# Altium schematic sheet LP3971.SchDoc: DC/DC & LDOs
size 419 x 266 mm; Date: May 24, 2007; DrawnBy: Yossi Har-Nov; Engineer: Yossi Har-Nov; DocumentNumber: 1; Revision: 1.0; SheetNumber: 1; SheetTotal: 3; PageSetup: Record=PageOptions|CenterHorizontal=True|CenterVertical=True|PrintScale=0.66|XCorrection=1.00|YCorrection=1.00|PrintKind=1|BorderSize=5000000|LeftOffset=0|BottomOffset=0|Orientation=2|PaperLength=2794|PaperWidth=2159|Scale=100|PaperSource=7|PrintQuality=600|MediaType=1|DitherType=2|PaperKind=Letter|PrintScaleMode=1
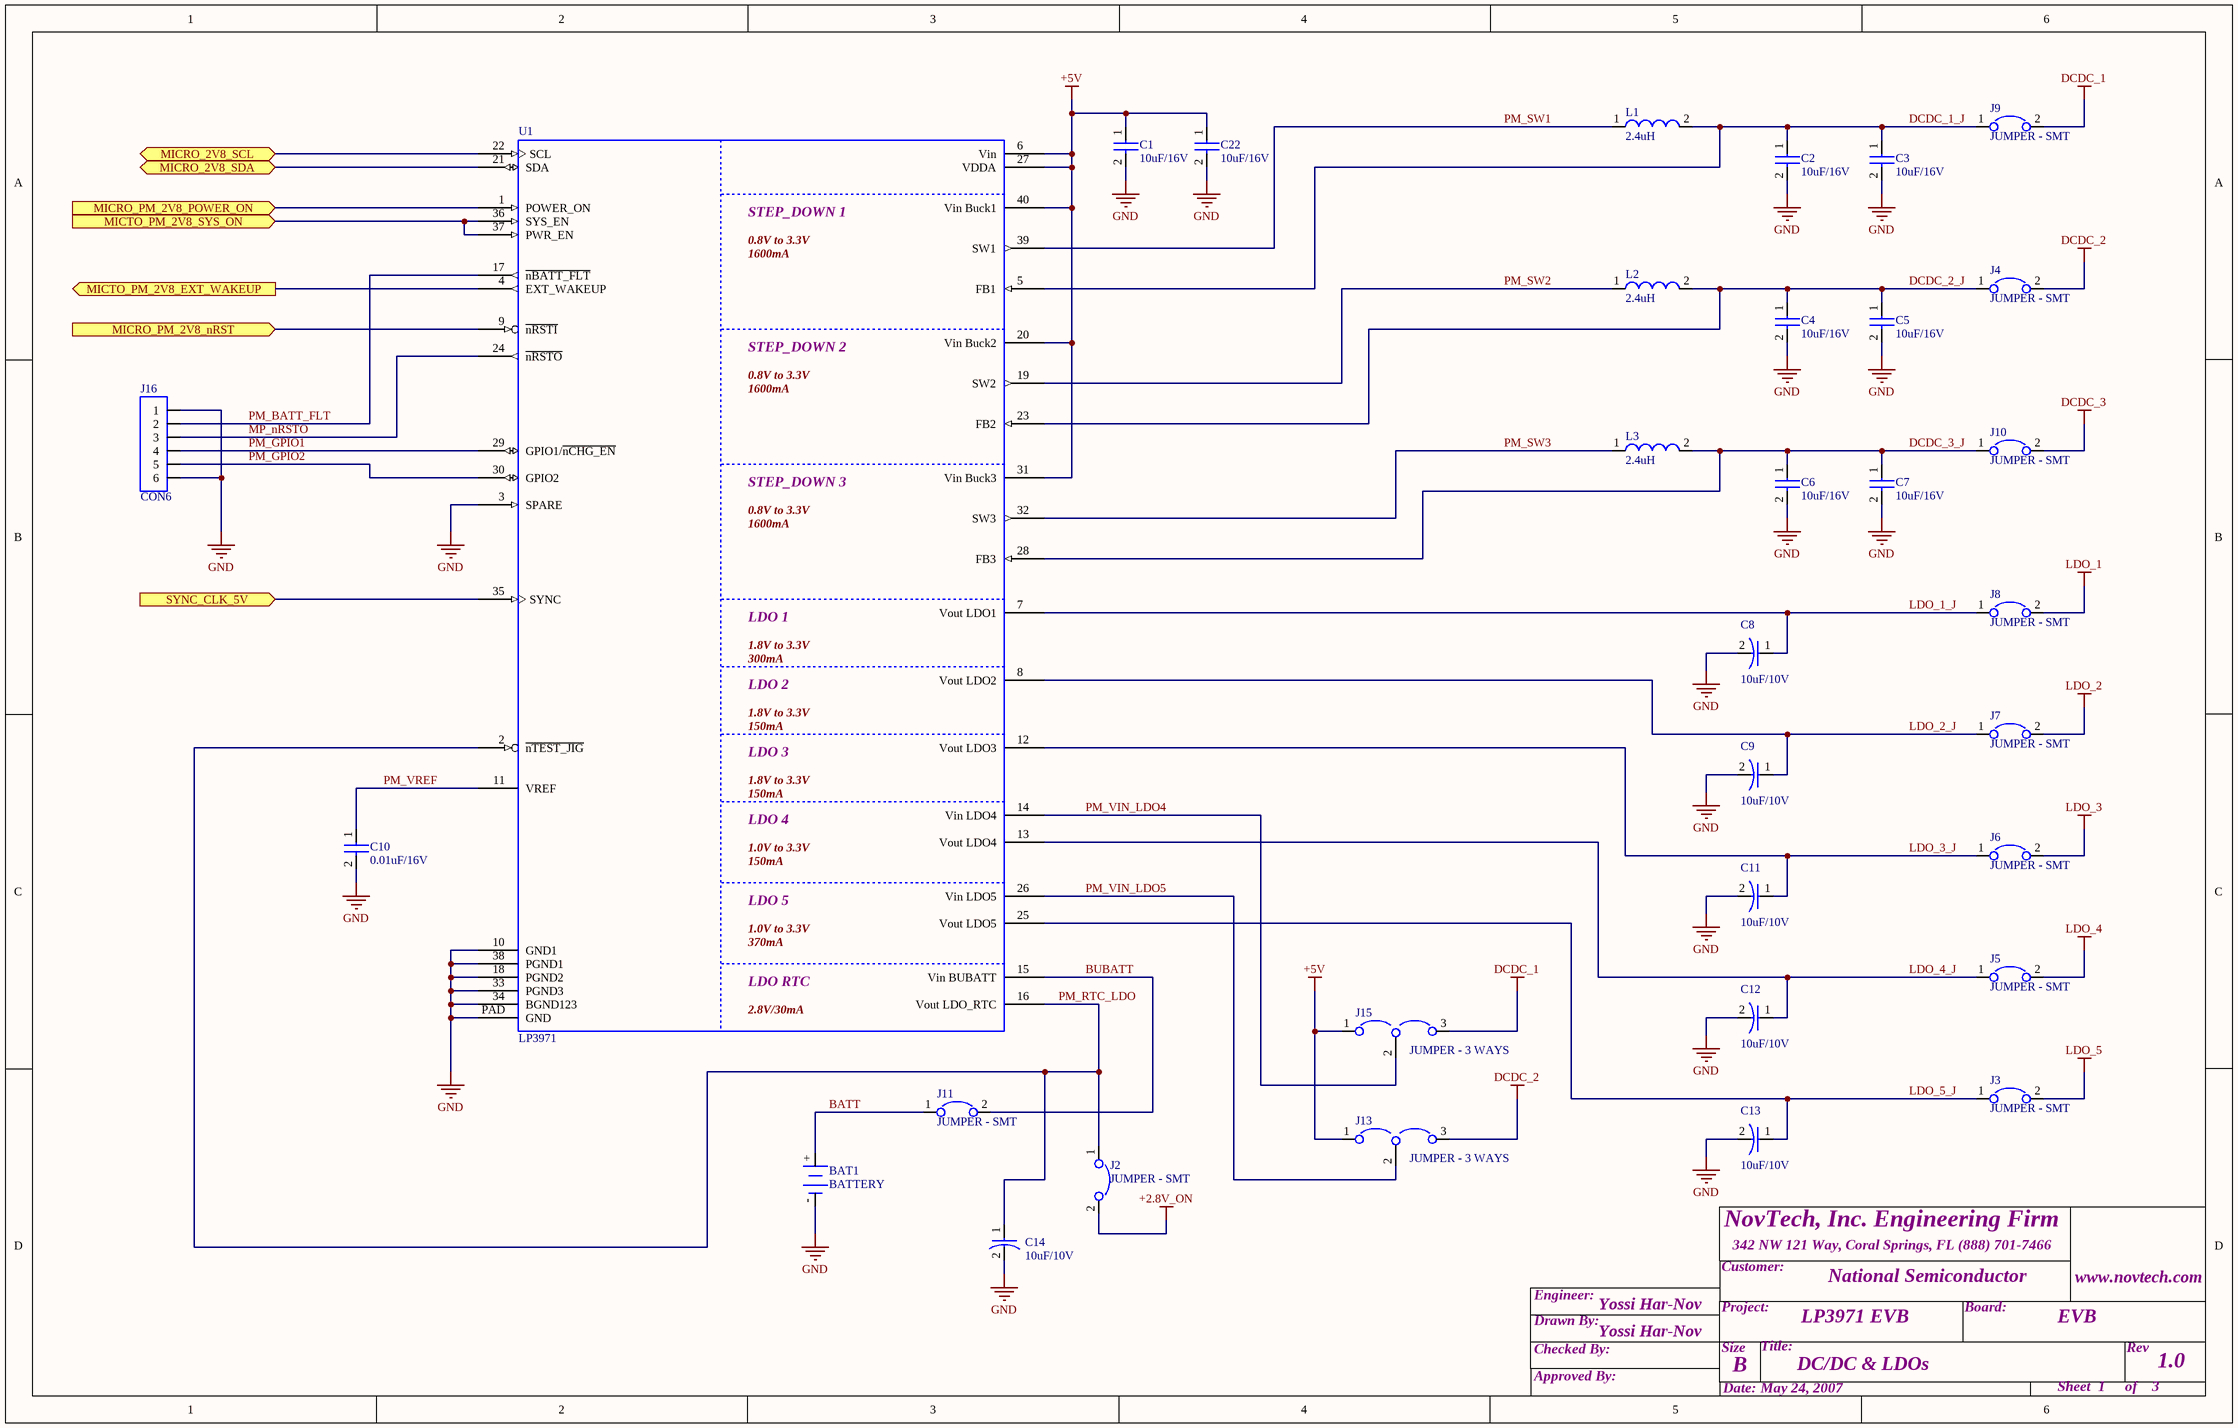
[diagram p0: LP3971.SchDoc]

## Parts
BAT1  BATTERY  [BATTERY ML2020]
C1  10uF/16V  [1210_C]
C2  10uF/16V  [1210_C]
C3  10uF/16V  [1210_C]
C4  10uF/16V  [1210_C]
C5  10uF/16V  [1210_C]
C6  10uF/16V  [1210_C]
C7  10uF/16V  [1210_C]
C8  10uF/10V  [A CASE (3216-18)]
C9  10uF/10V  [A CASE (3216-18)]
C10  0.01uF/16V  [0603_C]
C11  10uF/10V  [A CASE (3216-18)]
C12  10uF/10V  [A CASE (3216-18)]
C13  10uF/10V  [A CASE (3216-18)]
C14  10uF/10V  [A CASE (3216-18)]
C22  10uF/16V  [1210_C]
J2  JUMPER - SMT  [BH2-NP]
J3  JUMPER - SMT  [BH2-NP]
J4  JUMPER - SMT  [BH2-NP]
J5  JUMPER - SMT  [BH2-NP]
J6  JUMPER - SMT  [BH2-NP]
J7  JUMPER - SMT  [BH2-NP]
J8  JUMPER - SMT  [BH2-NP]
J9  JUMPER - SMT  [BH2-NP]
J10  JUMPER - SMT  [BH2-NP]
J11  JUMPER - SMT  [BH2-NP]
J13  JUMPER - 3 WAYS  [BH3-NP]
J15  JUMPER - 3 WAYS  [BH3-NP]
J16  CON6  [BH6-NP]
L1  2.4uH  [ELL6PM]
L2  2.4uH  [ELL6PM]
L3  2.4uH  [ELL6PM]
U1  LP3971  [QFN40P500X500X80-40N]

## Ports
MICRO_2V8_SCL (bidir), MICRO_2V8_SDA (bidir), MICRO_PM_2V8_nRST (in), MICRO_PM_2V8_POWER_ON (in), MICTO_PM_2V8_EXT_WAKEUP (out), MICTO_PM_2V8_SYS_ON (in), SYNC_CLK_5V (in)

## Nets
+2.8V_ON: J2.2
+5V: C1.1 C22.1 J13.1 J15.1 U1.6(Vin) U1.20(Vin_Buck2) U1.27(VDDA) U1.31(Vin_Buck3) U1.40(Vin_Buck1)
DCDC_1: J9.2 J15.3
DCDC_2: J4.2 J13.3
DCDC_3: J10.2
GND: BAT1.- C1.2 C2.2 C3.2 C4.2 C5.2 C6.2 C7.2 C8.2 C9.2 C10.2 C11.2 C12.2 C13.2 C14.2 C22.2 J16.1 J16.6 U1.3(SPARE) U1.10(GND1) U1.18(PGND2) U1.33(PGND3) U1.34(BGND123) U1.38(PGND1) U1.PAD(GND)
LDO_1: J8.2
LDO_2: J7.2
LDO_3: J6.2
LDO_4: J5.2
LDO_5: J3.2
BATT: BAT1.+ J11.1
BUBATT: J11.2 U1.15(Vin_BUBATT)
DCDC_1_J: C2.1 C3.1 J9.1 L1.2 U1.5(FB1)
DCDC_2_J: C4.1 C5.1 J4.1 L2.2 U1.23(FB2)
DCDC_3_J: C6.1 C7.1 J10.1 L3.2 U1.28(FB3)
LDO_1_J: C8.1 J8.1 U1.7(Vout_LDO1)
LDO_2_J: C9.1 J7.1 U1.8(Vout_LDO2)
LDO_3_J: C11.1 J6.1 U1.12(Vout_LDO3)
LDO_4_J: C12.1 J5.1 U1.13(Vout_LDO4)
LDO_5_J: C13.1 J3.1 U1.25(Vout_LDO5)
MICRO_2V8_SCL: U1.22(SCL) ; port MICRO_2V8_SCL
MICRO_2V8_SDA: U1.21(SDA) ; port MICRO_2V8_SDA
MICRO_PM_2V8_nRST: U1.9(~{nRSTI}) ; port MICRO_PM_2V8_nRST
MICRO_PM_2V8_POWER_ON: U1.1(POWER_ON) ; port MICRO_PM_2V8_POWER_ON
MICTO_PM_2V8_EXT_WAKEUP: U1.4(EXT_WAKEUP) ; port MICTO_PM_2V8_EXT_WAKEUP
MICTO_PM_2V8_SYS_ON: U1.36(SYS_EN) U1.37(PWR_EN) ; port MICTO_PM_2V8_SYS_ON
MP_nRSTO: J16.3 U1.24(~{nRSTO})
PM_BATT_FLT: J16.2 U1.17(~{nBATT_FLT})
PM_GPIO1: J16.4 U1.29(GPIO1/~{nCHG_EN})
PM_GPIO2: J16.5 U1.30(GPIO2)
PM_RTC_LDO: C14.1 J2.1 U1.2(~{nTEST_JIG}) U1.16(Vout_LDO_RTC)
PM_SW1: L1.1 U1.39(SW1)
PM_SW2: L2.1 U1.19(SW2)
PM_SW3: L3.1 U1.32(SW3)
PM_VIN_LDO4: J15.2 U1.14(Vin_LDO4)
PM_VIN_LDO5: J13.2 U1.26(Vin_LDO5)
PM_VREF: C10.1 U1.11(VREF)
SYNC_CLK_5V: U1.35(SYNC) ; port SYNC_CLK_5V

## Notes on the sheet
- National Semiconductor
- LP3971 EVB
- EVB

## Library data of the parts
BAT1 = BATTERY: PART: ML2020/H1C; MFG: Panasonic
C1-C7 C10 C22 = CAP_0603: Capasitor 0603footprint; Right: 20; Bottom: 10
C8 C9 C11-C14 = CAP_TANT: Right: 20; Bottom: 10
J13 J15 = JUMPER - SMT 3 WAYS: JUMPER - SMT
J16 = CON6: Right: 20; Bottom: 50
L1-L3 = INDUCTOR: PART: ELL-6PV2R4N; Right: 20; Bottom: 40; MFG: PANASONIC
U1 = LP3971: Power Management Unit for Advanced Application Processors; MFG: NATIONAL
